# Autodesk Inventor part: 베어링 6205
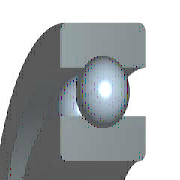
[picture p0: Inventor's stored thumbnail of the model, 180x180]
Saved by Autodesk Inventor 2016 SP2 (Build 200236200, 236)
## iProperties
Created: 2012-02
Part Number: 베어링 6205
Material: 강철, 연강
Description: 깊은 그루브 볼 베어링
Document SubType Name: Modeling
Standard: KS B 2023
Designer: mduedu
Standards Organization: KS
Language: ko-KR
Size Designation: 6205 - 25 x 52 x 15
Categories: <MemberInstance><Categories><Category DisplayName="샤프트 부품" InternalName="7f7aeb1f-a693-4053-b835-cee3144e0d98" Mnemonic="SHFT"><Category DisplayName="베어링" Inter
Density: 1 g/cm^3
Appearance: 노란색
IsCustomPart: 1
Author: mduedu
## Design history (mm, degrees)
sketch "스케치" dims "d0" = 7.02 (= -0.26 x WD + 0.26 x BD)
  geometry: L1 (3.99, 19.25)-(11.01, 19.25); L2 (7.5, 19.25)-(7.5, 15.74); L3 (7.5, 19.25)-(7.5, 22.76); L4 (4.892, 16.901)-(0, 16.901); L5 (0, 12.5)-(15, 12.5); L6 (4.892, 21.599)-(0, 21.599); L7 (0, 26)-(15, 26); L8 (15, 12.5)-(15, 16.901); L9 (10.108, 16.901)-(15, 16.901); L10 (10.108, 21.599)-(15, 21.599); L11 (15, 26)-(15, 21.599); L12 (-1.4, 0)-(8.4, 0) reference; L13 (0, -0.3)-(0, 5.3) reference
  constraints: 22 end point, 4 point on line, 2 collinear, 2 perpendicular, 2 symmetric about line, 1 midpoint, 1 parallel, 14 other
  dimensions: "d9" = 25 diameter of L5 L12 (= WD); "d11" = 52 diameter of L7 L12 (= BD); "d12" = 15 distance between parallel lines of L8 L13 (= KB); "d13" = 33.802 diameter of L9 L12 (= 0.326 x BD + 0.674 x WD)
revolve "본체" stored, may be unused: angle "d6" = 90 deg
revolve "볼" stored, may be unused: angle "d7" = 90 deg
pattern_circular "IDS_ARRAYBALL[SIMPL:T]" dims angle "d3" = 360 deg
body "Solid1"
fillet "모깎기1" dims "d1" = 1 (= KRS)
other parameters: "WD" = 25 [user parameter; used in 5 equation terms], "BD" = 52 [user parameter; used in 5 equation terms], "KB" = 15 [user parameter; used in 1 equation term], "KRS" = 1 [user parameter; used in 1 equation term], "d4" = 0, "d5" = 0, "d8" = 0, "d14" = 0, "d15" = 0, "BBA" = 0 [user parameter], "BC0" = 7800000 [user parameter], "BC" = 1.4e+07 [user parameter], "BR" = 26 (= 0.5 x BD) [user parameter], "WR" = 12.5 (= 0.5 x WD) [user parameter]
